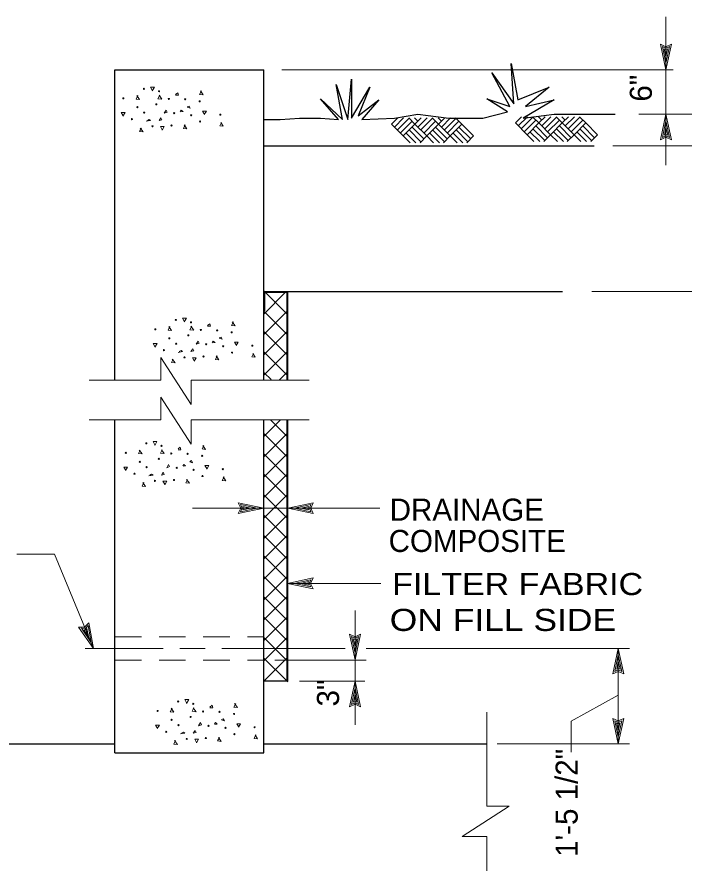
# Model space of a CAD drawing. Extents: x -28.1 to 13.9, y -16.1 to 13.9.
# Drawn here: x 2.598 to 6.374, y -4.35 to 0.44 of the extents above; entities that cross this region are included whole.
import ezdxf
from ezdxf.enums import TextEntityAlignment as Align

# ---------------------------------------------------------------- set-up
doc = ezdxf.new("R2010")
doc.units = 0
doc.header["$LTSCALE"] = 0.05
doc.linetypes.add('MEDIUM_DASHED', pattern=[4.5, 3, -1.5])
doc.layers.add('1', color=7, linetype='Continuous', lineweight=13)
doc.layers.add('2', color=7, linetype='Continuous', lineweight=13)

msp = doc.modelspace()

# ---------------------------------------------------------------- linework, layer by layer
at = {"layer": '1'}
for p, q in [((6.27196, 0.14069), (6.24096, 0.28469)), ((6.27196, 0.17769), (6.25196, 0.27169)), ((6.25196, 0.27169), (6.27196, 0.26269)), ((6.27196, 0.21369), (6.26196, 0.25869)), ((6.26196, 0.25869), (6.27196, 0.25469)), ((6.27196, 0.14069), (6.30296, 0.28469)), ((6.27196, 0.17769), (6.29196, 0.27169)), ((6.27196, 0.26269), (6.29196, 0.27169)), ((6.27196, 0.21369), (6.28096, 0.25869)), ((6.27196, 0.25469), (6.28096, 0.25869)), ((4.09796, 0.13969), (6.31196, 0.13969)), ((4.71896, -0.16731), (4.75396, -0.13231)), ((4.73496, -0.18431), (4.78696, -0.13231)), ((4.75196, -0.20031), (4.81796, -0.13431)), ((4.85096, -0.16731), (4.81596, -0.13231)), ((4.86796, -0.15131), (4.84896, -0.13231)), ((4.85096, -0.16731), (4.88696, -0.13231)), ((4.85096, -0.16731), (4.88696, -0.13231)), ((4.86796, -0.18431), (4.91996, -0.13231)), ((4.88496, -0.13431), (4.88196, -0.13231)), ((4.88496, -0.20031), (4.95096, -0.13431)), ((4.98396, -0.16731), (4.94896, -0.13231)), ((5.00096, -0.15131), (4.98196, -0.13231)), ((4.98396, -0.16731), (5.01996, -0.13231)), ((5.00096, -0.18431), (5.05296, -0.13231)), ((5.01796, -0.13431), (5.01496, -0.13231)), ((5.01796, -0.20031), (5.08396, -0.13431)), ((5.11696, -0.16731), (5.08096, -0.13231)), ((5.41996, -0.16031), (5.45496, -0.12531)), ((5.43596, -0.17731), (5.48796, -0.12531)), ((5.45296, -0.19331), (5.51896, -0.12731)), ((5.55196, -0.16031), (5.51696, -0.12531)), ((5.56896, -0.14431), (5.54996, -0.12531)), ((5.55196, -0.16031), (5.58796, -0.12531)), ((5.55196, -0.16031), (5.58796, -0.12531)), ((5.56896, -0.17731), (5.62096, -0.12531)), ((5.58596, -0.12731), (5.58296, -0.12531)), ((5.58596, -0.19331), (5.65196, -0.12731)), ((5.68496, -0.16031), (5.64996, -0.12531)), ((5.70196, -0.14431), (5.68296, -0.12531)), ((5.68496, -0.16031), (5.72096, -0.12531)), ((5.70196, -0.17731), (5.75396, -0.12531)), ((5.71896, -0.12731), (5.71596, -0.12531)), ((5.71896, -0.19331), (5.78496, -0.12731)), ((5.81796, -0.16031), (5.78196, -0.12531)), ((6.11896, -0.11131), (6.79896, -0.11131)), ((6.27196, -0.11131), (6.24096, -0.25531)), ((6.27196, -0.11131), (6.30296, -0.25531)), ((4.76796, -0.21831), (4.83496, -0.15131)), ((4.78496, -0.23431), (4.85096, -0.16731)), ((4.90096, -0.25131), (4.83496, -0.18431)), ((4.91796, -0.23431), (4.85096, -0.16731)), ((4.90096, -0.21831), (4.96796, -0.15131)), ((4.91796, -0.23431), (4.98396, -0.16731)), ((5.03396, -0.25131), (4.96796, -0.18431)), ((5.03396, -0.21831), (5.09996, -0.15131)), ((5.05096, -0.23431), (5.11696, -0.16731)), ((5.16696, -0.25131), (5.09996, -0.18431)), ((5.18296, -0.23431), (5.11696, -0.16731)), ((5.46896, -0.21131), (5.53596, -0.14431)), ((5.48596, -0.22731), (5.55196, -0.16031)), ((5.60196, -0.24431), (5.53596, -0.17731)), ((5.61896, -0.22731), (5.55196, -0.16031)), ((5.60196, -0.21131), (5.66896, -0.14431)), ((5.61896, -0.22731), (5.68496, -0.16031)), ((5.73496, -0.24431), (5.66896, -0.17731)), ((5.73496, -0.21131), (5.80096, -0.14431)), ((5.75196, -0.22731), (5.81796, -0.16031)), ((5.86796, -0.24431), (5.80096, -0.17731)), ((5.88396, -0.22731), (5.81796, -0.16031)), ((6.27196, -0.14831), (6.25196, -0.24231)), ((6.27196, -0.18431), (6.26296, -0.22931)), ((6.27196, -0.14831), (6.29196, -0.24231)), ((6.27196, -0.18431), (6.28196, -0.22931)), ((4.85596, -0.27231), (4.80096, -0.21831)), ((4.88496, -0.26731), (4.81796, -0.20031)), ((4.87996, -0.27231), (4.91796, -0.23431)), ((4.95596, -0.27231), (4.91796, -0.23431)), ((4.98996, -0.27231), (4.93496, -0.21831)), ((5.01796, -0.26731), (4.95096, -0.20031)), ((5.01196, -0.27231), (5.05096, -0.23431)), ((5.12196, -0.27231), (5.06696, -0.21831)), ((5.14996, -0.26731), (5.08396, -0.20031)), ((5.14496, -0.27231), (5.18296, -0.23431)), ((5.55696, -0.26531), (5.50196, -0.21131)), ((5.58596, -0.26031), (5.51896, -0.19331)), ((5.58096, -0.26531), (5.61896, -0.22731)), ((5.65696, -0.26531), (5.61896, -0.22731)), ((5.69096, -0.26531), (5.63596, -0.21131)), ((5.71896, -0.26031), (5.65196, -0.19331)), ((5.71296, -0.26531), (5.75196, -0.22731)), ((5.82296, -0.26531), (5.76796, -0.21131)), ((5.85096, -0.26031), (5.78496, -0.19331)), ((5.84596, -0.26531), (5.88396, -0.22731)), ((6.27196, -0.23331), (6.25196, -0.24231)), ((6.27196, -0.22531), (6.26296, -0.22931)), ((6.28196, -0.22931), (6.27196, -0.22531)), ((6.29196, -0.24231), (6.27196, -0.23331)), ((5.97196, -0.28931), (6.79896, -0.28931)), ((3.99496, -1.24231), (4.11696, -1.12031)), ((4.13096, -1.24631), (3.99696, -1.11231)), ((5.85196, -1.11531), (6.79896, -1.11531)), ((3.99496, -1.35731), (4.12896, -1.22331)), ((4.13096, -1.36131), (3.99696, -1.22731)), ((3.99496, -1.47331), (4.12896, -1.33931)), ((4.13096, -1.47731), (3.99696, -1.34331)), ((3.99496, -1.58831), (4.12896, -1.45431)), ((4.13096, -1.59231), (3.99696, -1.45831)), ((3.41196, -1.61631), (3.41196, -1.48831)), ((3.58396, -1.75431), (3.41196, -1.48831)), ((4.03596, -1.61231), (3.99696, -1.57431)), ((4.08196, -1.61731), (4.12896, -1.57031)), ((3.00596, -1.61631), (3.41196, -1.61631)), ((3.58396, -1.75431), (3.58396, -1.61631)), ((3.58396, -1.61631), (4.25196, -1.61631)), ((3.41196, -1.84031), (3.41196, -1.71231)), ((3.58396, -1.97831), (3.41196, -1.71231)), ((3.00596, -1.84031), (3.41196, -1.84031)), ((3.58396, -1.97831), (3.58396, -1.84031)), ((3.58396, -1.84031), (4.25196, -1.84031)), ((3.99496, -1.93531), (4.08896, -1.84131)), ((4.13096, -1.93931), (4.03296, -1.84131)), ((3.99496, -2.05031), (4.12896, -1.91631)), ((4.13096, -2.05431), (3.99696, -1.92031)), ((3.99496, -2.16631), (4.12896, -2.03231)), ((4.13096, -2.17031), (3.99696, -2.03631)), ((3.99496, -2.28131), (4.12896, -2.14731)), ((4.13096, -2.28531), (3.99696, -2.15131)), ((3.99496, -2.39731), (4.12896, -2.26331)), ((4.13096, -2.40131), (3.99696, -2.26731)), ((3.99496, -2.34131), (3.85096, -2.31031)), ((3.99496, -2.34131), (3.85096, -2.37231)), ((3.95796, -2.34131), (3.86396, -2.32131)), ((3.87296, -2.34131), (3.86396, -2.32131)), ((3.95796, -2.34131), (3.86396, -2.36131)), ((3.86396, -2.36131), (3.87296, -2.34131)), ((3.92196, -2.34131), (3.87696, -2.33231)), ((3.88096, -2.34131), (3.87696, -2.33231)), ((3.92196, -2.34131), (3.87696, -2.35131)), ((3.87696, -2.35131), (3.88096, -2.34131)), ((4.13096, -2.34131), (4.27496, -2.31031)), ((4.13096, -2.34131), (4.27496, -2.37231)), ((4.16796, -2.34131), (4.26196, -2.32131)), ((4.16796, -2.34131), (4.26196, -2.36131)), ((4.20396, -2.34131), (4.24896, -2.33131)), ((4.20396, -2.34131), (4.24896, -2.35031)), ((4.24896, -2.33131), (4.24496, -2.34131)), ((4.24496, -2.34131), (4.24896, -2.35031)), ((4.26196, -2.32131), (4.25296, -2.34131)), ((4.25296, -2.34131), (4.26196, -2.36131)), ((3.99496, -2.51231), (4.12896, -2.37831)), ((4.13096, -2.51631), (3.99696, -2.38231)), ((3.99496, -2.62831), (4.12896, -2.49431)), ((4.13096, -2.63231), (3.99696, -2.49831)), ((3.99496, -2.74331), (4.12896, -2.60931)), ((4.13096, -2.74731), (3.99696, -2.61331)), ((3.99496, -2.85931), (4.12896, -2.72531)), ((4.13096, -2.86331), (3.99696, -2.72931)), ((4.12996, -2.76731), (4.27396, -2.73631)), ((4.12996, -2.76731), (4.65796, -2.76731)), ((4.12996, -2.76731), (4.27396, -2.79831)), ((4.16696, -2.76731), (4.26096, -2.74731)), ((4.16696, -2.76731), (4.26096, -2.78731)), ((4.20296, -2.76731), (4.24796, -2.75731)), ((4.20296, -2.76731), (4.24796, -2.77631)), ((4.24796, -2.75731), (4.24396, -2.76731)), ((4.24396, -2.76731), (4.24796, -2.77631)), ((4.26096, -2.74731), (4.25196, -2.76731)), ((4.25196, -2.76731), (4.26096, -2.78731)), ((3.99496, -2.97431), (4.12896, -2.84031)), ((4.13096, -2.97831), (3.99696, -2.84431)), ((3.99496, -3.09031), (4.12896, -2.95631)), ((4.13096, -3.09431), (3.99696, -2.96031)), ((3.03096, -3.13531), (2.94696, -3.01431)), ((2.98496, -3.02231), (2.99996, -3.00631)), ((3.01696, -3.10131), (2.99996, -3.00631)), ((3.03096, -3.13531), (3.00496, -2.99031)), ((3.01696, -3.10131), (2.96296, -3.02131)), ((2.96296, -3.02131), (2.98496, -3.02231)), ((3.00296, -3.06831), (2.97696, -3.03031)), ((2.97696, -3.03031), (2.98796, -3.03031)), ((2.98796, -3.03031), (2.99396, -3.02231)), ((3.00296, -3.06831), (2.99396, -3.02231)), ((4.51196, -3.19931), (4.48096, -3.05531)), ((4.51196, -3.19931), (4.54296, -3.05531)), ((3.99496, -3.20531), (4.12896, -3.07131)), ((4.13096, -3.20931), (3.99696, -3.07531)), ((4.51196, -3.16231), (4.49196, -3.06831)), ((4.49196, -3.06831), (4.51196, -3.07731)), ((4.51196, -3.12631), (4.50196, -3.08131)), ((4.50196, -3.08131), (4.51196, -3.08531)), ((4.51196, -3.16231), (4.53196, -3.06831)), ((4.51196, -3.07731), (4.53196, -3.06831)), ((4.51196, -3.12631), (4.52096, -3.08131)), ((4.51196, -3.08531), (4.52096, -3.08131)), ((2.98296, -3.13531), (3.42596, -3.13531)), ((3.51996, -3.13531), (3.66296, -3.13531)), ((3.75696, -3.13531), (4.45596, -3.13531)), ((4.57396, -3.13531), (6.06496, -3.13531)), ((6.00196, -3.13531), (5.97096, -3.27931)), ((4.13096, -3.32531), (3.99396, -3.18831)), ((3.99496, -3.32131), (4.12896, -3.18731)), ((4.05796, -3.20231), (4.57496, -3.20231)), ((6.00196, -3.17231), (5.98196, -3.26631)), ((6.00196, -3.20831), (5.99296, -3.25331)), ((6.00196, -3.17231), (6.02196, -3.26631)), ((6.00196, -3.20831), (6.01196, -3.25331)), ((6.00196, -3.24931), (5.99296, -3.25331)), ((6.01196, -3.25331), (6.00196, -3.24931)), ((6.00196, -3.25731), (5.98196, -3.26631)), ((6.02196, -3.26631), (6.00196, -3.25731)), ((4.19796, -3.32131), (4.56796, -3.32131)), ((4.51196, -3.32131), (4.48096, -3.46531)), ((4.51196, -3.32131), (4.54296, -3.46531)), ((4.51196, -3.35831), (4.49196, -3.45231)), ((4.51196, -3.39431), (4.50296, -3.43931)), ((4.51196, -3.35831), (4.53196, -3.45231)), ((4.51196, -3.39431), (4.52196, -3.43931)), ((4.51196, -3.44331), (4.49196, -3.45231)), ((4.51196, -3.43531), (4.50296, -3.43931)), ((4.52196, -3.43931), (4.51196, -3.43531)), ((4.53196, -3.45231), (4.51196, -3.44331)), ((5.25696, -4.02831), (5.25696, -3.49631)), ((6.00196, -3.67531), (5.97096, -3.53131)), ((6.00196, -3.63831), (5.98196, -3.54431)), ((5.98196, -3.54431), (6.00196, -3.55331)), ((6.00196, -3.67531), (6.03296, -3.53131)), ((6.00196, -3.63831), (6.02196, -3.54431)), ((6.00196, -3.55331), (6.02196, -3.54431)), ((6.00196, -3.60231), (5.99196, -3.55731)), ((5.99196, -3.55731), (6.00196, -3.56131)), ((6.00196, -3.60231), (6.01096, -3.55731)), ((6.00196, -3.56131), (6.01096, -3.55731)), ((5.31596, -3.67531), (6.06496, -3.67531)), ((5.11896, -4.20031), (5.38496, -4.02831)), ((5.25696, -4.02831), (5.38496, -4.02831)), ((5.11896, -4.20031), (5.25696, -4.20031)), ((5.25696, -4.20031), (5.25696, -4.88531))]:
    msp.add_line(p, q, dxfattribs=at)
at = {"layer": '1', "lineweight": 25}
for p, q in [((3.15196, -1.61631), (3.15196, 0.13969)), ((3.15196, 0.13969), (3.99496, 0.13969)), ((3.99496, -1.61631), (3.99496, 0.13969)), ((3.99496, -0.28931), (5.86596, -0.28931)), ((3.99496, -1.11531), (5.68696, -1.11531)), ((3.15196, -3.72631), (3.15196, -1.84031)), ((3.99496, -3.72631), (3.99496, -1.84031)), ((4.12996, -3.32131), (3.99496, -3.32131)), ((1.92496, -3.67531), (3.15196, -3.67531)), ((3.99496, -3.67531), (5.25596, -3.67531)), ((3.15196, -3.72631), (3.99496, -3.72631))]:
    msp.add_line(p, q, dxfattribs=at)
at = {"layer": '1', "lineweight": 40}
for p, q in [((4.12996, -1.61631), (4.12996, -1.11531)), ((4.12996, -3.32131), (4.12996, -1.84031))]:
    msp.add_line(p, q, dxfattribs=at)
at = {"layer": '1', "linetype": 'MEDIUM_DASHED'}
for p, q in [((3.15196, -3.06931), (3.99496, -3.06931)), ((3.15196, -3.20231), (3.99496, -3.20231))]:
    msp.add_line(p, q, dxfattribs=at)
at = {"layer": '1'}
for points in [[(6.27196, -0.40031), (6.27196, -0.11131), (6.27196, 0.14069), (6.27196, 0.43969)], [(6.24096, 0.28469), (6.27196, 0.27069), (6.30296, 0.28469)], [(5.08896, -0.27231), (4.98396, -0.16731), (5.01996, -0.13231)], [(5.78996, -0.26531), (5.68496, -0.16031), (5.72096, -0.12531)], [(4.82296, -0.27231), (4.78496, -0.23431), (4.71896, -0.16731)], [(5.52396, -0.26531), (5.48596, -0.22731), (5.41996, -0.16031)], [(6.30296, -0.25531), (6.27196, -0.24131), (6.24096, -0.25531)], [(3.59196, -2.34131), (3.99496, -2.34131), (4.13096, -2.34131), (4.65196, -2.34131)], [(3.85096, -2.37231), (3.86496, -2.34131), (3.85096, -2.31031)], [(4.27496, -2.31031), (4.26096, -2.34131), (4.27496, -2.37231)], [(3.03096, -3.13531), (2.81096, -2.60131), (2.59796, -2.60131)], [(4.27396, -2.73631), (4.25996, -2.76731), (4.27396, -2.79831)], [(4.51196, -3.56831), (4.51196, -3.32131), (4.51196, -3.19931), (4.51196, -2.92131)], [(2.94696, -3.01431), (2.98096, -3.01531), (3.00496, -2.99031)], [(4.48096, -3.05531), (4.51196, -3.06931), (4.54296, -3.05531)], [(6.00196, -3.67531), (6.00196, -3.13531), (6.03296, -3.27931)], [(6.03296, -3.27931), (6.00196, -3.26531), (5.97096, -3.27931)], [(5.73596, -3.72231), (5.73596, -3.54731), (6.00196, -3.40031)], [(4.54296, -3.46531), (4.51196, -3.45131), (4.48096, -3.46531)], [(5.97096, -3.53131), (6.00196, -3.54531), (6.03296, -3.53131)]]:
    msp.add_lwpolyline(points, dxfattribs=at)
at = {"layer": '1', "lineweight": 25}
msp.add_lwpolyline([(3.99496, -0.14131), (4.08796, -0.14131), (4.19796, -0.13331), (4.31596, -0.13331), (4.41896, -0.14131), (4.31596, -0.02331), (4.44096, -0.14131), (4.40396, 0.05769), (4.46996, -0.14131), (4.49196, 0.08669), (4.49196, -0.13331), (4.59496, 0.04269), (4.52896, -0.11931), (4.64596, -0.03031), (4.55096, -0.14131), (4.73496, -0.13331), (4.86696, -0.11131), (5.04296, -0.13331), (5.23496, -0.13331), (5.37396, -0.09731), (5.25696, -0.02331), (5.38896, -0.06731), (5.28596, 0.12369), (5.41096, -0.05231), (5.39596, 0.17569), (5.43296, -0.03031), (5.60996, 0.04269), (5.47696, -0.06731), (5.63896, -0.03031), (5.46296, -0.13331), (5.63896, -0.11131), (5.85996, -0.11131), (5.98496, -0.11131)], dxfattribs=at)
at = {"layer": '1', "lineweight": 40}
msp.add_lwpolyline([(4.12996, -1.11931), (3.99796, -1.11931), (3.99796, -1.22431)], dxfattribs=at)
at = {"layer": '2'}
for p, q in [((3.49596, 0.00069), (3.50796, 0.01069)), ((3.67696, -1.30731), (3.68896, -1.29731)), ((3.50996, -2.00631), (3.52196, -1.99631)), ((3.68996, -3.46731), (3.70196, -3.45731))]:
    msp.add_line(p, q, dxfattribs=at)
for points in [[(3.36396, 0.02469), (3.35396, 0.04269), (3.37596, 0.04269), (3.36396, 0.02069)], [(3.50796, 0.01069), (3.51196, -0.00331), (3.49596, -0.00331)], [(3.64196, 0.02069), (3.63196, 0.00069), (3.65196, -0.00131), (3.63596, 0.02069)], [(3.28196, -0.00531), (3.27196, -0.02531), (3.29196, -0.02731), (3.27596, -0.00531)], [(3.40596, -0.00331), (3.39596, -0.02331), (3.41796, -0.02531), (3.40196, -0.00331)], [(3.52196, -0.09531), (3.52796, -0.08731), (3.53796, -0.09531), (3.52396, -0.09731)], [(3.56196, -0.06931), (3.57196, -0.06531), (3.57796, -0.07731), (3.56196, -0.07131)], [(3.65796, -0.10931), (3.64796, -0.09331), (3.66996, -0.09331), (3.65796, -0.11331)], [(3.19796, -0.11731), (3.18796, -0.10131), (3.20996, -0.10131), (3.19796, -0.12131)], [(3.33596, -0.14731), (3.34596, -0.14131), (3.35396, -0.14731), (3.32996, -0.15131)], [(3.30196, -0.18931), (3.29196, -0.20931), (3.31196, -0.21131), (3.29596, -0.18931)], [(3.41996, -0.19931), (3.40996, -0.18131), (3.43196, -0.18131), (3.41996, -0.20131)], [(3.54996, -0.17131), (3.53996, -0.19131), (3.55996, -0.19331), (3.54396, -0.17131)], [(3.75596, -0.15731), (3.74596, -0.17731), (3.76596, -0.17931), (3.75196, -0.15731)], [(3.54496, -1.28331), (3.53496, -1.26531), (3.55696, -1.26531), (3.54496, -1.28731)], [(3.82296, -1.28731), (3.81296, -1.30731), (3.83296, -1.30931), (3.81696, -1.28731)], [(3.46296, -1.31331), (3.45296, -1.33331), (3.47296, -1.33531), (3.45696, -1.31331)], [(3.58696, -1.31131), (3.57696, -1.33131), (3.59896, -1.33331), (3.58296, -1.31131)], [(3.68896, -1.29731), (3.69296, -1.31131), (3.67696, -1.31131)], [(3.74296, -1.37731), (3.75296, -1.37331), (3.75896, -1.38531), (3.74296, -1.37931)], [(3.37896, -1.42531), (3.36896, -1.40931), (3.39096, -1.40931), (3.37896, -1.42931)], [(3.70296, -1.40331), (3.70896, -1.39531), (3.71896, -1.40331), (3.70496, -1.40531)], [(3.83896, -1.41731), (3.82896, -1.40131), (3.85096, -1.40131), (3.83896, -1.42131)], [(3.51696, -1.45531), (3.52696, -1.44931), (3.53496, -1.45531), (3.51096, -1.45931)], [(3.73096, -1.47931), (3.72096, -1.49931), (3.74096, -1.50131), (3.72496, -1.47931)], [(3.93696, -1.46531), (3.92696, -1.48531), (3.94696, -1.48731), (3.93296, -1.46531)], [(3.48296, -1.49731), (3.47296, -1.51731), (3.49296, -1.51931), (3.47696, -1.49731)], [(3.60096, -1.50731), (3.59096, -1.48931), (3.61296, -1.48931), (3.60096, -1.50931)], [(3.37796, -1.98231), (3.36796, -1.96431), (3.38996, -1.96431), (3.37796, -1.98631)], [(3.41996, -2.01031), (3.40996, -2.03031), (3.43196, -2.03231), (3.41596, -2.01031)], [(3.52196, -1.99631), (3.52596, -2.01031), (3.50996, -2.01031)], [(3.65596, -1.98631), (3.64596, -2.00631), (3.66596, -2.00831), (3.64996, -1.98631)], [(3.29596, -2.01231), (3.28596, -2.03231), (3.30596, -2.03431), (3.28996, -2.01231)], [(3.53596, -2.10231), (3.54196, -2.09431), (3.55196, -2.10231), (3.53796, -2.10431)], [(3.57596, -2.07631), (3.58596, -2.07231), (3.59196, -2.08431), (3.57596, -2.07831)], [(3.67196, -2.11631), (3.66196, -2.10031), (3.68396, -2.10031), (3.67196, -2.12031)], [(3.21196, -2.12431), (3.20196, -2.10831), (3.22396, -2.10831), (3.21196, -2.12831)], [(3.34996, -2.15431), (3.35996, -2.14831), (3.36796, -2.15431), (3.34396, -2.15831)], [(3.31596, -2.19631), (3.30596, -2.21631), (3.32596, -2.21831), (3.30996, -2.19631)], [(3.43396, -2.20631), (3.42396, -2.18831), (3.44596, -2.18831), (3.43396, -2.20831)], [(3.56396, -2.17831), (3.55396, -2.19831), (3.57396, -2.20031), (3.55796, -2.17831)], [(3.76996, -2.16431), (3.75996, -2.18431), (3.77996, -2.18631), (3.76596, -2.16431)], [(3.55796, -3.44331), (3.54796, -3.42531), (3.56996, -3.42531), (3.55796, -3.44731)], [(3.83596, -3.44731), (3.82596, -3.46731), (3.84596, -3.46931), (3.82996, -3.44731)], [(3.47596, -3.47331), (3.46596, -3.49331), (3.48596, -3.49531), (3.46996, -3.47331)], [(3.59996, -3.47131), (3.58996, -3.49131), (3.61196, -3.49331), (3.59596, -3.47131)], [(3.70196, -3.45731), (3.70596, -3.47131), (3.68996, -3.47131)], [(3.75596, -3.53731), (3.76596, -3.53331), (3.77196, -3.54531), (3.75596, -3.53931)], [(3.39196, -3.58531), (3.38196, -3.56931), (3.40396, -3.56931), (3.39196, -3.58931)], [(3.71596, -3.56331), (3.72196, -3.55531), (3.73196, -3.56331), (3.71796, -3.56531)], [(3.85196, -3.57731), (3.84196, -3.56131), (3.86396, -3.56131), (3.85196, -3.58131)], [(3.52996, -3.61531), (3.53996, -3.60931), (3.54796, -3.61531), (3.52396, -3.61931)], [(3.74396, -3.63931), (3.73396, -3.65931), (3.75396, -3.66131), (3.73796, -3.63931)], [(3.94996, -3.62531), (3.93996, -3.64531), (3.95996, -3.64731), (3.94596, -3.62531)], [(3.49596, -3.65731), (3.48596, -3.67731), (3.50596, -3.67931), (3.48996, -3.65731)], [(3.61396, -3.66731), (3.60396, -3.64931), (3.62596, -3.64931), (3.61396, -3.66931)]]:
    msp.add_lwpolyline(points, dxfattribs=at)
for points in [[(3.43196, -0.10531), (3.44196, -0.08731), (3.44796, -0.09931)], [(3.40196, -0.14731), (3.41196, -0.13131), (3.41796, -0.14331)], [(3.61296, -1.41331), (3.62296, -1.39531), (3.62896, -1.40731)], [(3.58296, -1.45531), (3.59296, -1.43931), (3.59896, -1.45131)], [(3.44596, -2.11231), (3.45596, -2.09431), (3.46196, -2.10631)], [(3.41596, -2.15431), (3.42596, -2.13831), (3.43196, -2.15031)], [(3.62596, -3.57331), (3.63596, -3.55531), (3.64196, -3.56731)], [(3.59596, -3.61531), (3.60596, -3.59931), (3.61196, -3.61131)]]:
    msp.add_lwpolyline(points, close=True, dxfattribs=at)
for centre in [(3.31646, 0.03244), (3.40196, 0.01894), (3.19996, -0.02106), (3.45746, -0.02456), (3.54996, -0.02656), (3.63246, -0.03806), (3.27946, -0.07156), (3.38696, -0.05506), (3.24896, -0.13906), (3.31796, -0.10206), (3.48796, -0.10556), (3.58396, -0.11706), (3.74896, -0.11356), (3.36496, -0.17956), (3.47296, -0.17456), (3.63446, -0.15256), (3.49746, -1.27556), (3.58296, -1.28906), (3.38096, -1.32906), (3.63846, -1.33256), (3.73096, -1.33456), (3.46046, -1.37956), (3.56796, -1.36306), (3.81346, -1.34606), (3.49896, -1.41006), (3.66896, -1.41356), (3.76496, -1.42506), (3.92996, -1.42156), (3.42996, -1.44706), (3.54596, -1.48756), (3.65396, -1.48256), (3.81546, -1.46056), (3.33046, -1.97456), (3.41596, -1.98806), (3.21396, -2.02806), (3.40096, -2.06206), (3.47146, -2.03156), (3.56396, -2.03356), (3.64646, -2.04506), (3.29346, -2.07856), (3.33196, -2.10906), (3.26296, -2.14606), (3.50196, -2.11256), (3.59796, -2.12406), (3.76296, -2.12056), (3.37896, -2.18656), (3.48696, -2.18156), (3.64846, -2.15956), (3.51046, -3.43556), (3.59596, -3.44906), (3.39396, -3.48906), (3.65146, -3.49256), (3.74396, -3.49456), (3.47346, -3.53956), (3.58096, -3.52306), (3.82646, -3.50606), (3.51196, -3.57006), (3.68196, -3.57356), (3.77796, -3.58506), (3.94296, -3.58156), (3.44296, -3.60706), (3.66696, -3.64256), (3.82846, -3.62056), (3.55896, -3.64756)]:
    msp.add_circle(centre, 0.00325, dxfattribs=at)

# ---------------------------------------------------------------- texts
at = {"layer": '1'}
for s, p in [('6"', (6.19196, 0.03631)), ('3"', (4.42096, -3.38773))]:
    msp.add_text(s, height=0.125, rotation=90, dxfattribs=at).set_placement(p, align=Align.CENTER)
for s, p in [('DRAINAGE', (4.70796, -2.41231)), ('COMPOSITE', (4.70196, -2.58931))]:
    msp.add_text(s, height=0.125, dxfattribs=at).set_placement(p)
for s, width, p in [('FILTER FABRIC', 1.15, (4.72196, -2.83331)), ('ON FILL SIDE', 1.2, (4.70796, -3.03631))]:
    msp.add_text(s, height=0.125, dxfattribs=dict(at, width=width)).set_placement(p)
msp.add_text('1\'-5 1/2"', height=0.125, rotation=90, dxfattribs=at).set_placement((5.77196, -4.31531))

doc.saveas('drawing.dxf')
